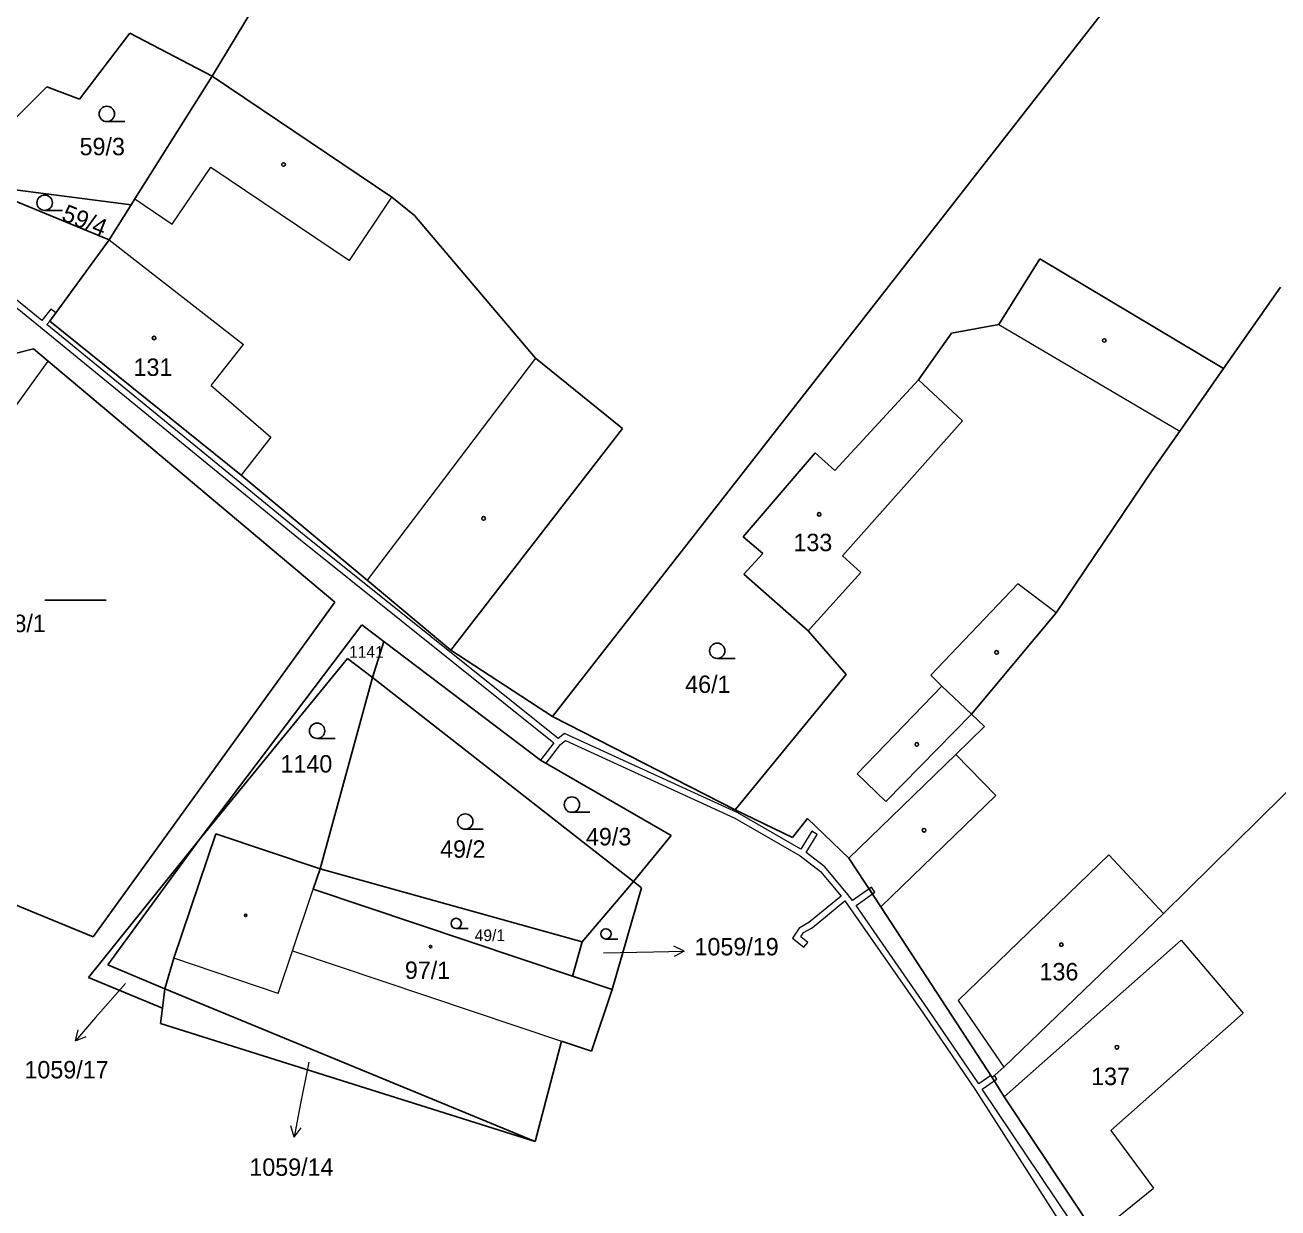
# Model space of a CAD drawing. Extents: x -694609 to -690140, y -1033292 to -1029794.
# Drawn here: x -692731.5 to -692609.2, y -1031318.8 to -1031203.3 of the extents above; entities that cross this region are included whole.
import ezdxf
from ezdxf.enums import TextEntityAlignment as Align

# ---------------------------------------------------------------- set-up
doc = ezdxf.new("R2010")
doc.units = 0
doc.header["$LTSCALE"] = 0.68
for name, color, linetype, lineweight in [('1', 7, 'Continuous', 25), ('13', 7, 'Continuous', 13), ('3', 7, 'Continuous', 25), ('4', 7, 'Continuous', 13), ('5', 7, 'Continuous', 25), ('7', 7, 'Continuous', 13)]:
    doc.layers.add(name, color=color, linetype=linetype, lineweight=lineweight)
doc.layers.add('2', color=7, linetype='Continuous')

msp = doc.modelspace()

# ---------------------------------------------------------------- linework, layer by layer
at = {"layer": '1'}
for p, q in [((-692693.76, -1031176.11), (-692713.25, -1031208.3)), ((-692680, -1031270.83), (-692614.65, -1031187.18)), ((-692726.2, -1031210.56), (-692721.29, -1031204.09)), ((-692721.29, -1031204.09), (-692713.25, -1031208.3)), ((-692713.25, -1031208.3), (-692720.79, -1031220.28)), ((-692713.25, -1031208.3), (-692695.68, -1031220.11)), ((-692738.2, -1031218.14), (-692729.38, -1031209.33)), ((-692729.38, -1031209.33), (-692726.2, -1031210.56)), ((-692736.3, -1031218.93), (-692721.16, -1031220.86)), ((-692723.31, -1031224.28), (-692736.3, -1031218.93)), ((-692720.79, -1031220.28), (-692721.16, -1031220.86)), ((-692695.68, -1031220.11), (-692693.48, -1031221.89)), ((-692721.16, -1031220.86), (-692723.31, -1031224.28)), ((-692693.48, -1031221.89), (-692681.68, -1031235.83)), ((-692723.31, -1031224.28), (-692729.1, -1031232.22)), ((-692636.42, -1031232.55), (-692632.43, -1031226.13)), ((-692632.43, -1031226.13), (-692614.48, -1031236.85)), ((-692608.91, -1031228.9), (-692614.48, -1031236.85)), ((-692710.42, -1031247.25), (-692729.1, -1031232.22)), ((-692641.06, -1031233.4), (-692636.42, -1031232.55)), ((-692644.28, -1031237.95), (-692641.06, -1031233.4)), ((-692738.98, -1031236.99), (-692730.69, -1031234.93)), ((-692730.69, -1031234.93), (-692729.26, -1031236.13)), ((-692729.26, -1031236.13), (-692701.25, -1031259.66)), ((-692681.68, -1031235.83), (-692673.16, -1031242.71)), ((-692614.48, -1031236.85), (-692616.66, -1031239.96)), ((-692652.43, -1031246.81), (-692644.28, -1031237.95)), ((-692616.66, -1031239.96), (-692618.75, -1031242.95)), ((-692689.92, -1031264.33), (-692673.16, -1031242.71)), ((-692618.75, -1031242.95), (-692621.45, -1031246.8)), ((-692661.38, -1031253.26), (-692654.36, -1031245.06)), ((-692654.36, -1031245.06), (-692652.43, -1031246.81)), ((-692710.42, -1031247.25), (-692698.11, -1031257.51)), ((-692621.45, -1031246.8), (-692630.83, -1031260.68)), ((-692659.48, -1031254.89), (-692661.38, -1031253.26)), ((-692659.48, -1031254.89), (-692661.32, -1031256.91)), ((-692655.03, -1031262.45), (-692661.32, -1031256.91)), ((-692698.11, -1031257.51), (-692689.92, -1031264.33)), ((-692701.25, -1031259.66), (-692724.87, -1031292.31)), ((-692630.83, -1031260.68), (-692639.1, -1031270.6)), ((-692698.61, -1031261.88), (-692714.5, -1031282.87)), ((-692698.61, -1031261.88), (-692696.46, -1031263.5)), ((-692651.32, -1031266.73), (-692655.03, -1031262.45)), ((-692696.46, -1031263.5), (-692697.58, -1031267)), ((-692696.46, -1031263.5), (-692681.17, -1031275.07)), ((-692680, -1031270.83), (-692689.92, -1031264.33)), ((-692714.5, -1031282.87), (-692700.03, -1031265.15)), ((-692700.03, -1031265.15), (-692697.58, -1031267)), ((-692702.7, -1031285.68), (-692697.58, -1031267)), ((-692697.58, -1031267), (-692672.1, -1031286.92)), ((-692651.32, -1031266.73), (-692662.16, -1031279.93)), ((-692639.1, -1031270.6), (-692637.82, -1031271.8)), ((-692680, -1031270.83), (-692662.16, -1031279.93)), ((-692637.82, -1031271.8), (-692640.62, -1031274.51)), ((-692602.76, -1031272.69), (-692620.34, -1031290.06)), ((-692681.17, -1031275.07), (-692668.42, -1031282.42)), ((-692640.62, -1031274.51), (-692651.07, -1031284.63)), ((-692724.87, -1031292.31), (-692759.55, -1031278.14)), ((-692662.16, -1031279.93), (-692656.57, -1031282.64)), ((-692656.57, -1031282.64), (-692655.1, -1031280.78)), ((-692655.1, -1031280.78), (-692651.07, -1031284.63)), ((-692725.3, -1031296.3), (-692714.5, -1031282.87)), ((-692723.42, -1031295.07), (-692714.5, -1031282.87)), ((-692716.98, -1031294.41), (-692712.89, -1031282.26)), ((-692712.89, -1031282.26), (-692702.7, -1031285.68)), ((-692668.42, -1031282.42), (-692672.1, -1031286.92)), ((-692647.94, -1031289.4), (-692651.07, -1031284.63)), ((-692703.37, -1031287.67), (-692702.7, -1031285.68)), ((-692702.7, -1031285.68), (-692677.1, -1031292.81)), ((-692703.37, -1031287.67), (-692678.05, -1031296.18)), ((-692672.1, -1031286.92), (-692677.1, -1031292.81)), ((-692671.31, -1031287.54), (-692674.17, -1031297.48)), ((-692672.1, -1031286.92), (-692671.31, -1031287.54)), ((-692637.08, -1031306.05), (-692647.94, -1031289.4)), ((-692620.34, -1031290.06), (-692635.94, -1031305.06)), ((-692677.1, -1031292.81), (-692678.05, -1031296.18)), ((-692717.85, -1031297.4), (-692723.42, -1031295.07)), ((-692717.85, -1031297.4), (-692716.98, -1031294.41)), ((-692718.08, -1031299.29), (-692725.3, -1031296.3)), ((-692678.05, -1031296.18), (-692674.17, -1031297.48)), ((-692717.85, -1031297.4), (-692718.08, -1031299.29)), ((-692681.69, -1031312.29), (-692717.85, -1031297.4)), ((-692676.19, -1031303.49), (-692674.17, -1031297.48)), ((-692718.08, -1031299.29), (-692718.27, -1031300.78)), ((-692718.27, -1031300.78), (-692681.69, -1031312.29)), ((-692679.14, -1031302.5), (-692681.69, -1031312.29)), ((-692679.14, -1031302.5), (-692676.19, -1031303.49)), ((-692635.94, -1031305.06), (-692637.08, -1031306.05)), ((-692635.9, -1031307.93), (-692637.08, -1031306.05)), ((-692626.97, -1031321.4), (-692635.9, -1031307.93))]:
    msp.add_line(p, q, dxfattribs=at)
at = {"layer": '13'}
for points in [[(-692733.15, -1031230.25), (-692730, -1031232.82), (-692704.62, -1031253.56), (-692679.87, -1031273.39), (-692681.17, -1031275.07), (-692680.64, -1031275.38), (-692679.23, -1031273.55), (-692678.74, -1031273.16), (-692662.21, -1031280.75), (-692655.81, -1031284.43), (-692653.85, -1031285.94), (-692651.82, -1031288.34), (-692654.98, -1031290.93), (-692655.92, -1031291.47), (-692656.56, -1031292.46), (-692655.46, -1031293.33), (-692655.09, -1031292.89), (-692655.76, -1031292.32), (-692655.5, -1031291.91), (-692654.64, -1031291.43), (-692651.45, -1031288.82), (-692643.83, -1031299.76), (-692638.71, -1031307.28), (-692629.89, -1031321.09)], [(-692649.1, -1031287.64), (-692650.73, -1031288.78), (-692651.16, -1031288.19), (-692653.43, -1031285.5), (-692655.25, -1031284.1), (-692654.18, -1031282.32), (-692654.69, -1031282.01), (-692655.75, -1031283.77), (-692661.91, -1031280.23), (-692678.82, -1031272.46), (-692679.45, -1031272.96), (-692704.24, -1031253.1), (-692729.39, -1031232.54), (-692729.1, -1031232.22), (-692728.5, -1031231.4), (-692728.98, -1031231.05), (-692729.86, -1031232.16), (-692732.67, -1031229.87)], [(-692607.05, -1031351.51), (-692615.47, -1031341.28), (-692614.4, -1031340.54), (-692614.88, -1031339.88), (-692615.96, -1031340.63), (-692619.21, -1031335.26), (-692638.05, -1031307.19), (-692636.87, -1031306.38), (-692637.08, -1031306.05), (-692637.2, -1031305.87), (-692638.38, -1031306.69), (-692643.33, -1031299.42), (-692650.36, -1031289.25), (-692648.77, -1031288.14), (-692649.1, -1031287.64)]]:
    msp.add_lwpolyline(points, dxfattribs=at)
for points in [[(-692649.1, -1031287.64), (-692648.77, -1031288.14), (-692648.52, -1031287.97), (-692648.85, -1031287.47)], [(-692637.08, -1031306.05), (-692636.87, -1031306.38), (-692636.63, -1031306.21), (-692636.85, -1031305.85)]]:
    msp.add_lwpolyline(points, close=True, dxfattribs=at)
at = {"layer": '3'}
for p, q in [((-692723.523, -1031212.74), (-692721.773, -1031212.74)), ((-692729.593, -1031221.41), (-692727.843, -1031221.41)), ((-692729.589, -1031259.46), (-692723.589, -1031259.46)), ((-692663.923, -1031265.15), (-692662.173, -1031265.15)), ((-692702.993, -1031272.96), (-692701.243, -1031272.96)), ((-692678.113, -1031280.17), (-692676.363, -1031280.17)), ((-692688.523, -1031281.82), (-692686.773, -1031281.82)), ((-692689.405, -1031291.52), (-692688.233, -1031291.52)), ((-692674.785, -1031292.54), (-692673.613, -1031292.54))]:
    msp.add_line(p, q, dxfattribs=at)
for centre, radius in [((-692723.5229, -1031211.9898), 0.75), ((-692729.5929, -1031220.6598), 0.75), ((-692663.9229, -1031264.3998), 0.75), ((-692702.9929, -1031272.2098), 0.75), ((-692678.1129, -1031279.4198), 0.75), ((-692688.5229, -1031281.0698), 0.75), ((-692689.4052, -1031291.0174), 0.5025), ((-692674.7852, -1031292.0374), 0.5025)]:
    msp.add_circle(centre, radius, dxfattribs=at)
at = {"layer": '4'}
for p, q in [((-692717.13, -1031222.76), (-692713.38, -1031217.19)), ((-692713.38, -1031217.19), (-692699.84, -1031226.29)), ((-692720.79, -1031220.28), (-692717.13, -1031222.76)), ((-692699.84, -1031226.29), (-692695.68, -1031220.11)), ((-692723.31, -1031224.28), (-692710.19, -1031234.51)), ((-692636.42, -1031232.55), (-692618.75, -1031242.95)), ((-692713.35, -1031238.51), (-692710.19, -1031234.51)), ((-692758.49, -1031276.61), (-692729.26, -1031236.13)), ((-692681.68, -1031235.83), (-692698.11, -1031257.51)), ((-692713.35, -1031238.51), (-692707.52, -1031243.56)), ((-692707.52, -1031243.56), (-692710.42, -1031247.25)), ((-692641.98, -1031267.84), (-692643.08, -1031266.79)), ((-692641.98, -1031267.84), (-692650.25, -1031276.42)), ((-692639.1, -1031270.6), (-692641.98, -1031267.84)), ((-692647.45, -1031279.12), (-692639.1, -1031270.6)), ((-692636.72, -1031278.53), (-692640.62, -1031274.51)), ((-692647.45, -1031279.12), (-692650.25, -1031276.42)), ((-692636.72, -1031278.53), (-692647.94, -1031289.4)), ((-692625.68, -1031284.31), (-692620.34, -1031290.06)), ((-692705.39, -1031293.68), (-692703.37, -1031287.67)), ((-692635.9, -1031307.93), (-692618.62, -1031292.65)), ((-692706.79, -1031297.84), (-692705.39, -1031293.68)), ((-692705.39, -1031293.68), (-692679.14, -1031302.5)), ((-692706.79, -1031297.84), (-692716.98, -1031294.41)), ((-692625.5, -1031311.22), (-692621.32, -1031316.87)), ((-692626.97, -1031321.4), (-692621.32, -1031316.87))]:
    msp.add_line(p, q, dxfattribs=at)
for points in [[(-692644.28, -1031237.95), (-692639.96, -1031241.96), (-692651.7, -1031255.14)], [(-692651.7, -1031255.14), (-692649.9, -1031256.75), (-692655.03, -1031262.45)], [(-692630.83, -1031260.68), (-692634.56, -1031257.87), (-692643.08, -1031266.79)], [(-692625.68, -1031284.31), (-692640.41, -1031298.53), (-692635.94, -1031305.06)], [(-692618.62, -1031292.65), (-692612.57, -1031299.76), (-692625.5, -1031311.22)]]:
    msp.add_lwpolyline(points, dxfattribs=at)
at = {"layer": '5'}
for centre, radius in [((-692706.2668, -1031216.9292), 0.175), ((-692718.9068, -1031233.8692), 0.175), ((-692626.1368, -1031234.1092), 0.175), ((-692653.9668, -1031251.0792), 0.175), ((-692686.7368, -1031251.4792), 0.175), ((-692636.6468, -1031264.5592), 0.175), ((-692644.4368, -1031273.5392), 0.175), ((-692643.7268, -1031281.9192), 0.175), ((-692709.9546, -1031290.2294), 0.1172), ((-692691.9146, -1031293.2794), 0.1172), ((-692630.3268, -1031293.0892), 0.175), ((-692624.8968, -1031303.0992), 0.175)]:
    msp.add_circle(centre, radius, dxfattribs=at)
at = {"layer": '7'}
for p, q in [((-692667.139, -1031293.728), (-692668.15, -1031293.244)), ((-692726.589, -1031302.475), (-692725.554, -1031302.048)), ((-692705.243, -1031311.866), (-692704.56, -1031310.978))]:
    msp.add_line(p, q, dxfattribs=at)
for points in [[(-692675.02, -1031293.89), (-692670.14, -1031293.78), (-692667.139, -1031293.728), (-692668.132, -1031294.246)], [(-692721.71, -1031296.88), (-692724.62, -1031300.21), (-692726.589, -1031302.475), (-692726.31, -1031301.391)], [(-692703.79, -1031304.57), (-692704.67, -1031308.92), (-692705.243, -1031311.866), (-692705.543, -1031310.787)]]:
    msp.add_lwpolyline(points, dxfattribs=at)

# ---------------------------------------------------------------- texts
at = {"layer": '2'}
for s, height, p in [('59/3', 1.7, (-692723.969, -1031216.025)), ('131', 1.7, (-692719.019, -1031237.565)), ('133', 1.7, (-692654.589, -1031254.675)), ('48/1', 1.7, (-692731.689, -1031262.575)), ('1141', 1.14, (-692698.179, -1031265.085)), ('46/1', 1.7, (-692664.839, -1031268.515)), ('1140', 1.7, (-692704.04, -1031276.285)), ('49/3', 1.7, (-692674.529, -1031283.395)), ('49/2', 1.7, (-692688.769, -1031284.605)), ('49/1', 1.14, (-692686.12, -1031292.745)), ('97/1', 1.7, (-692692.209, -1031296.435)), ('136', 1.7, (-692630.559, -1031296.575)), ('137', 1.7, (-692625.519, -1031306.795))]:
    msp.add_text(s, height=height, dxfattribs=at).set_placement(p, align=Align.CENTER)
msp.add_text('59/4', height=1.7, rotation=338, dxfattribs=at).set_placement((-692725.9969, -1031223.1687), align=Align.CENTER)
msp.add_text('1059/19', height=1.7, dxfattribs=at).set_placement((-692666.14, -1031294.135))
for s, p in [('1059/17', (-692723.35, -1031306.145)), ('1059/14', (-692701.39, -1031315.655))]:
    msp.add_text(s, height=1.7, dxfattribs=at).set_placement(p, align=Align.RIGHT)

doc.saveas('drawing.dxf')
